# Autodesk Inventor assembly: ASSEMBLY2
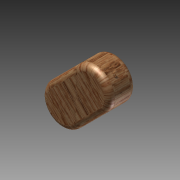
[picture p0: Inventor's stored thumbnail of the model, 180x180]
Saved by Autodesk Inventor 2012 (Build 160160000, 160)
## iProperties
Created: 2011-01
Part Number: ASSEMBLY2
Document SubType Name: Assembly
Designer: Microsoft
Author: Microsoft
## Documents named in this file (6)
- C:\Users\David\Desktop\Playground\3D work\Locket\ASSEMBLY2.iam
- C:\Users\David\Desktop\Playground\3D work\Locket\BASE2-TOP.ipt
- C:\Users\David\Desktop\Playground\3D work\Locket\BASE2.ipt
- C:\Users\David\Desktop\Playground\3D work\Locket\TOP2.ipt
- C:\Users\David\Desktop\Playground\3D work\Locket\BASE1.ipt
- C:\Users\David\Desktop\Playground\3D work\Locket\TOP1.ipt
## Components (5 placed, 5 different names)
1. BASE2-TOP:1 — Mate:3, Flush:2, Mate:4, Flush:3, Mate:5, Mate:7
2. BASE2:1 — Mate:3, Flush:2, Mate:4, Mate:6, Mate:8
3. TOP2:1 — Flush:3, Mate:5, Mate:6, Flush:4
4. BASE1:1 — Mate:1, Flush:1, Mate:2, Mate:7, Flush:4, Mate:8
5. TOP1:1 — Mate:1, Flush:1, Mate:2
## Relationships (12: Mate 8, Flush 4)
- Mate:1: BASE1:1 ↔ TOP1:1
- Flush:1: BASE1:1 ↔ TOP1:1
- Mate:2: BASE1:1 ↔ TOP1:1
- Mate:3: BASE2-TOP:1 ↔ BASE2:1
- Flush:2: BASE2-TOP:1 ↔ BASE2:1
- Mate:4: BASE2-TOP:1 ↔ BASE2:1
- Flush:3: BASE2-TOP:1 ↔ TOP2:1
- Mate:5: BASE2-TOP:1 ↔ TOP2:1
- Mate:6: BASE2:1 ↔ TOP2:1
- Mate:7: BASE2-TOP:1 ↔ BASE1:1
- Flush:4: TOP2:1 ↔ BASE1:1
- Mate:8: BASE2:1 ↔ BASE1:1
